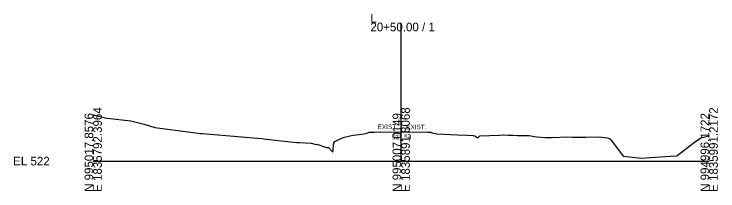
# Model space of a CAD drawing. Extents: x -26 to 2403, y -10 to 9558.
# Drawn here: x 974.3 to 1202.8, y 4990.3 to 5047.8 of the extents above; entities that cross this region are included whole.
import ezdxf

# ---------------------------------------------------------------- set-up
doc = ezdxf.new("R2010")
doc.units = 0
for name, color, linetype in [('Exist Cross Section Cell', 7, 'Continuous'), ('Exist XS Center Line Elevation Label', 7, 'Continuous'), ('Exist XS Ground Line', 7, 'Continuous'), ('Prop XS SE Text', 7, 'Continuous'), ('Scratch_Level_6', 7, 'Continuous')]:
    doc.layers.add(name, color=color, linetype=linetype)

msp = doc.modelspace()

# ---------------------------------------------------------------- linework, layer by layer
at = {"layer": 'Exist Cross Section Cell'}
for p, q in [((1100, 5000), (1100, 5044.98)), ((1000, 5000), (1100, 5000)), ((1100, 5000), (1200, 5000))]:
    msp.add_line(p, q, dxfattribs=at)
at = {"layer": 'Exist XS Ground Line'}
msp.add_lwpolyline([(1000, 5014.99), (1004.42, 5013.92), (1004.43, 5013.91), (1004.48, 5013.91), (1012.22, 5013.04), (1016.53, 5011.99), (1019.98, 5010.95), (1031.62, 5009.39), (1034.79, 5008.98), (1035.5, 5008.93), (1048.2, 5007.92), (1054.63, 5007.31), (1055.4, 5007.22), (1058.09, 5006.95), (1064.11, 5006.27), (1066.16, 5006.03), (1066.99, 5006.01), (1070.8, 5005.83), (1070.81, 5005.83), (1072.43, 5005.43), (1072.65, 5005.45), (1075.8, 5004.46), (1076.39, 5004.46), (1077.84, 5002.88), (1078.13, 5005.92), (1078.4, 5006.33), (1079.78, 5007.04), (1081.07, 5007.59), (1081.2, 5007.63), (1083.89, 5008.32), (1084.54, 5008.47), (1087.96, 5008.89), (1088.86, 5009.11), (1089.63, 5009.35), (1090.7, 5009.43), (1091.31, 5009.45), (1099.92, 5009.54), (1100, 5009.54), (1108.59, 5009.4), (1109.3, 5009.39), (1109.58, 5009.35), (1109.77, 5009.31), (1110.02, 5009.22), (1111.55, 5008.89), (1118.25, 5008.57), (1121.46, 5008.45), (1123.36, 5008.35), (1123.94, 5008.22), (1124.85, 5007.61), (1125.57, 5008.18), (1131.85, 5008.46), (1133.36, 5008.49), (1134.89, 5008.44), (1136.29, 5008.4), (1137.77, 5008.33), (1141.49, 5008.32), (1144.08, 5007.91), (1146.8, 5007.64), (1147.58, 5007.68), (1149.17, 5007.64), (1154, 5007.91), (1155.46, 5007.8), (1159.99, 5007.8), (1164.23, 5007.94), (1166.89, 5007.54), (1167.75, 5007.25), (1168.54, 5006.36), (1172.06, 5001.56), (1175.13, 5001.26), (1177.76, 5000.98), (1187.34, 5001.6), (1189.52, 5001.7), (1195.26, 5006.17), (1197.28, 5007.55), (1198.98, 5008), (1200, 5008.26)], dxfattribs=at)

# ---------------------------------------------------------------- texts
at = {"layer": 'Exist Cross Section Cell'}
for s, p in [('L', (1090, 5044.98)), ('20+50.00 / 1', (1090, 5042.18)), ('EL 522', (974, 4998.6))]:
    msp.add_text(s, height=2.8, dxfattribs=at).set_placement(p)
for s, p in [('E 1835792.3964', (1002.8, 4990)), ('E 1835891.8068', (1102.8, 4990)), ('E 1835991.2172', (1202.8, 4990)), ('N 995017.8576', (1000, 4990)), ('N 995007.0149', (1100, 4990)), ('N 994996.1722', (1200, 4990))]:
    msp.add_text(s, height=2.8, rotation=90, dxfattribs=at).set_placement(p)
at = {"layer": 'Exist XS Center Line Elevation Label'}
msp.add_text('531.54', height=1.5, dxfattribs=at).set_placement((1096.96, 5007.04))
at = {"layer": 'Prop XS SE Text'}
for rotation, p in [(0.0001, (1092.38, 5010.4)), (359.4243, (1101.65, 5010.38))]:
    msp.add_text('EXIST.', height=1.5, rotation=rotation, dxfattribs=at).set_placement(p)
at = {"layer": 'Scratch_Level_6'}
msp.add_text('-', height=0.01, dxfattribs=at).set_placement((1000, 4999.99))

doc.saveas('drawing.dxf')
